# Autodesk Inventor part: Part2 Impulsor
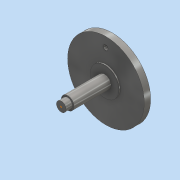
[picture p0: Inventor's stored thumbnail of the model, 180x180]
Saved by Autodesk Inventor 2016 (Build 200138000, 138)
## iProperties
Created: 2015-11
Part Number: Part2 Impulsor
Material: Steel, Alloy
Document SubType Name: Modeling
Designer: SanPer86
Density: 7.73 g/cm^3
Appearance: Semi-Polished
Author: SanPer86
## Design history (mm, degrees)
sketch "Sketch1"
  geometry: L1 (0, 0)-(0, 4.5); L2 (-1.485, 4)-(-3, 4); L3 (-3, 4)-(-3, 3.5); L4 (-3, 3.5)-(-1.125, 3.5); L5 (-0.5, 3.4)-(-0.5, 0.5); L6 (-0.5, 0.5)-(-0.375, 0.5); L7 (-0.375, 0.5)-(-0.375, 0); L8 (-0.375, 0)-(0, 0); L9 (-0.5, 3.4)-(-1.125, 3.4); L10 (-1.125, 3.4)-(-1.125, 3.5); L11 (-1.485, 4)-(-1.485, 4.5); L12 (-1.485, 4.5)-(0, 4.5)
  constraints: 24 end point, 6 perpendicular, 2 horizontal, 2 vertical, 1 parallel
  dimensions: "d6" = 6 diameter of L2.end L1; "d17" = 0.75 diameter of L7.end L1; "d18" = 0.5 vertical distance of L7.end L5.end; "d22" = 0.1 distance of L9.end L4.end; "d24" = 0.5 distance of L3.end L2.end; "d25" = 1 diameter of L5 L1; "d26" = 4.5 distance of L1.start L1.end; "d39" = 0.5 vertical distance of L2.end L11.end; "d44" = 2.97 diameter of L11.end L1; "d45" = 2.25 diameter of L10 L1
revolve "Revolution1" sketch "Sketch1" stored, may be unused: angle "d27" = 90 deg
sketch "Sketch2" dims "d28" = 4.5
  geometry: C1 r 3 at (0, 0) reference; C2 r 0.188 at (-0.017, -2.25); 2 further points
  constraints: 1 centre point, 1 coincident, 3 other
  dimensions: "d29" = 0.375 diameter of C2
extrude "Extrusion1" cut sketch "Sketch2" distance "d30" = 0.5; taper "d31" = 0 deg
sketch "Sketch6"
  geometry: C1 r 2.6 at (-0.009, -3); 2 further points
  constraints: 1 centre point, 2 other
  dimensions: "d41" = 5.2 diameter of C1
extrude "Extrusion3" cut sketch "Sketch6" distance "d42" = 0.5; taper "d43" = 0 deg
body "Solid1"
